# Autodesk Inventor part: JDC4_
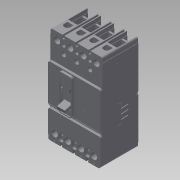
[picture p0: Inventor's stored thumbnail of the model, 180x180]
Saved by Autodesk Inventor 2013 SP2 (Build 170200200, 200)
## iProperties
Created: 2014-08
Part Number: JDC4_
Material: Generic
Document SubType Name: Modeling
Designer: DM/JS
Density: 1 g/cm^3
Description: TYPE JDC THERMAL MAGNETIC CIRCUIT BREAKERS FOUR POLE, SERIES C
MXEDIT: false
MXINVTNRV: INV Versioned Component|JDC4_|004.0
Author: DM/JS
Revision Number: 004
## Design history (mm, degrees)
derived "JD4_.iam"
node "L1"
node "L2"
node "L3"
node "L4"
node "T1"
node "T2"
node "T3"
node "T4"
sketch "Sketch1"
  geometry: C1 r 8.738 at (7.775, 1.905) reference; C2 r 8.738 at (42.7, 1.905) reference; C3 r 8.738 at (77.65, 1.905) reference; C4 r 8.738 at (112.575, 1.905) reference; C5 r 10.795 at (112.575, 213.843) reference; C6 r 10.795 at (77.65, 213.843) reference; C7 r 10.795 at (42.7, 213.843) reference; C8 r 10.795 at (7.775, 213.843) reference; 1 further point
extrude "Extrusion2" cut sketch "Sketch1" stored distance "d3" = 25.4; taper "d4" = 0 deg
sketch "Sketch2"
  geometry: C1 r 10.795 at (4.604, 7.974) reference; C2 r 10.795 at (-30.321, 7.974) reference; C3 r 8.738 at (-30.321, -203.964) reference; C4 r 8.738 at (4.604, -203.964) reference; 1 further point
extrude "Extrusion3" cut sketch "Sketch2" stored distance "d5" = 25.4; taper "d6" = 0 deg
sketch "Sketch3"
  geometry: L1 (17.475, 0)-(0, 0) reference; L2 (0, 0)-(0, -23.069) reference; L3 (0, -23.069)-(17.475, -23.069) reference; L4 (17.475, -23.069)-(17.475, 0) reference; L5 (4.572, -8.794)-(4.572, -11.969) reference; L6 (12.903, -11.969)-(12.903, -8.794) reference; L7 (52.4, 0)-(34.925, 0) reference; L8 (34.925, 0)-(34.925, -23.069) reference; L9 (34.925, -23.069)-(52.4, -23.069) reference; L10 (52.4, -23.069)-(52.4, 0) reference; L11 (39.497, -8.794)-(39.497, -11.969) reference; L12 (47.828, -11.969)-(47.828, -8.794) reference; L13 (87.351, 0)-(69.875, 0) reference; L14 (69.875, 0)-(69.875, -23.069) reference; L15 (69.875, -23.069)-(87.351, -23.069) reference; L16 (87.351, -23.069)-(87.351, 0) reference; L17 (74.447, -8.794)-(74.447, -11.969) reference; L18 (82.779, -11.969)-(82.779, -8.794) reference; L19 (122.276, 0)-(104.8, 0) reference; L20 (104.8, 0)-(104.8, -23.069) reference; L21 (104.8, -23.069)-(122.276, -23.069) reference; L22 (122.276, -23.069)-(122.276, 0) reference; L23 (109.372, -8.794)-(109.372, -11.969) reference; L24 (117.704, -11.969)-(117.704, -8.794) reference; A1 r 4.166 centre (8.738, -8.794) between (12.903, -8.794) and (4.572, -8.794) reference; A2 r 4.166 centre (8.738, -11.969) between (4.572, -11.969) and (12.903, -11.969) reference; A3 r 4.166 centre (43.663, -8.794) between (47.828, -8.794) and (39.497, -8.794) reference; A4 r 4.166 centre (43.663, -11.969) between (39.497, -11.969) and (47.828, -11.969) reference; A5 r 4.166 centre (78.613, -8.794) between (82.779, -8.794) and (74.447, -8.794) reference; A6 r 4.166 centre (78.613, -11.969) between (74.447, -11.969) and (82.779, -11.969) reference; A7 r 4.166 centre (113.538, -8.794) between (117.704, -8.794) and (109.372, -8.794) reference; A8 r 4.166 centre (113.538, -11.969) between (109.372, -11.969) and (117.704, -11.969) reference; 1 further point
extrude "Extrusion4" join sketch "Sketch3" stored distance "d7" = 25.4; taper "d8" = 0 deg
body "Solid1"
node "JD4_FIX.ipt:1"
node "JD4_FIX2.ipt:1"
body "Solid2"
node "Projected Loop1"
node "Projected Loop2"
node "Projected Loop3"
node "Projected Loop4"
